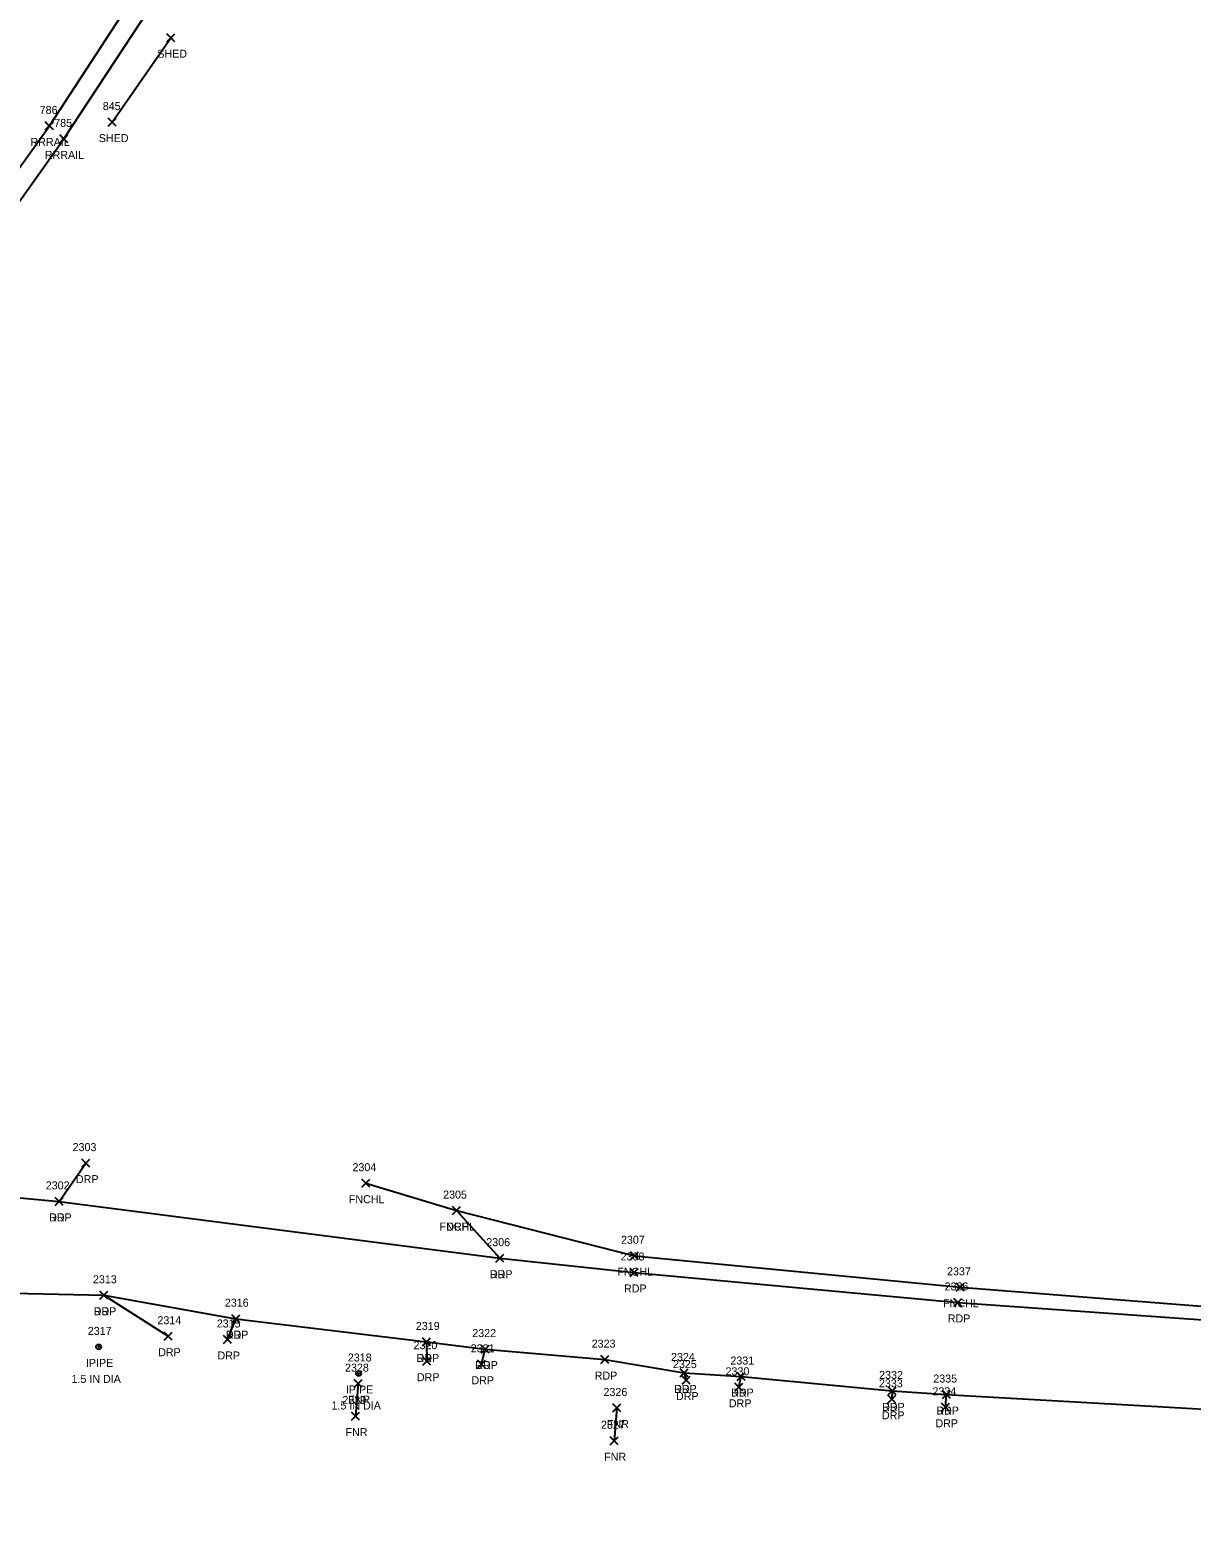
# Model space of a CAD drawing. Extents: x 1767353 to 1772625, y 740790 to 747702.
# Drawn here: x 1770625.6 to 1770915.9, y 742358.6 to 742730.2 of the extents above; entities that cross this region are included whole.
import ezdxf

# ---------------------------------------------------------------- set-up
doc = ezdxf.new("R2010")
doc.units = 0
for name, color, linetype in [('L_A', 7, 'Continuous'), ('L_I', 7, 'Continuous'), ('L_TIC', 7, 'Continuous'), ('LBC', 7, 'Continuous'), ('LFNC', 7, 'Continuous'), ('M_A', 7, 'Continuous'), ('M_C', 7, 'Continuous'), ('M_I', 7, 'Continuous'), ('MPIP', 7, 'Continuous'), ('P_A', 7, 'Continuous'), ('P_I', 7, 'Continuous'), ('P_TIC', 7, 'Continuous'), ('PET', 7, 'Continuous'), ('R_A', 7, 'Continuous'), ('R_I', 7, 'Continuous'), ('R_TIC', 7, 'Continuous'), ('RDP', 7, 'Continuous'), ('RR', 7, 'Continuous')]:
    doc.layers.add(name, color=color, linetype=linetype)

msp = doc.modelspace()

# ---------------------------------------------------------------- linework, layer by layer
at = {"layer": 'L_TIC'}
for points in [[(1770659.86, 742727.2), (1770661.86, 742729.2)], [(1770661.86, 742727.2), (1770659.86, 742729.2)], [(1770645.24, 742706.1), (1770647.24, 742708.1)], [(1770647.24, 742706.1), (1770645.24, 742708.1)], [(1770708.62, 742440.85), (1770710.62, 742442.85)], [(1770710.62, 742440.85), (1770708.62, 742442.85)], [(1770731.27, 742434), (1770733.27, 742436)], [(1770733.27, 742434), (1770731.27, 742436)], [(1770775.72, 742422.71), (1770777.72, 742424.71)], [(1770777.72, 742422.71), (1770775.72, 742424.71)], [(1770857.12, 742414.82), (1770859.12, 742416.82)], [(1770859.12, 742414.82), (1770857.12, 742416.82)], [(1770706.67, 742390.75), (1770708.67, 742392.75)], [(1770708.67, 742390.75), (1770706.67, 742392.75)], [(1770771.33, 742384.66), (1770773.33, 742386.66)], [(1770773.33, 742384.66), (1770771.33, 742386.66)], [(1770706.01, 742382.63), (1770708.01, 742384.63)], [(1770708.01, 742382.63), (1770706.01, 742384.63)], [(1770770.64, 742376.47), (1770772.64, 742378.47)], [(1770772.64, 742376.47), (1770770.64, 742378.47)]]:
    msp.add_lwpolyline(points, dxfattribs=at)
at = {"layer": 'LBC'}
msp.add_lwpolyline([(1770646.24, 742707.1), (1770660.86, 742728.2)], dxfattribs=at)
at = {"layer": 'LFNC'}
for points in [[(1770709.62, 742441.85), (1770732.27, 742435), (1770776.72, 742423.71), (1770858.12, 742415.82), (1770944.87, 742409.03), (1770965.3, 742411.95), (1770974.89, 742413.7), (1770984.8, 742417.23), (1770993.55, 742422.55), (1771009.31, 742433.08), (1771022.79, 742448.82), (1771027.82, 742457.07), (1771031.96, 742466.17), (1771043.36, 742521.94), (1771054.49, 742575.63), (1771058.48, 742593.36), (1771072.95, 742667.16), (1771097.46, 742789.3), (1771131.95, 742961.2), (1771147.21, 743037.58), (1771136.95, 743059.9)], [(1770707.67, 742391.75), (1770707.01, 742383.63)], [(1770772.33, 742385.66), (1770771.64, 742377.47)]]:
    msp.add_lwpolyline(points, dxfattribs=at)
at = {"layer": 'MPIP'}
for centre, radius in [((1770642.83, 742400.93), 0.625), ((1770642.83, 742400.93), 0.0833), ((1770707.8, 742394.28), 0.625), ((1770707.8, 742394.28), 0.0833)]:
    msp.add_circle(centre, radius, dxfattribs=at)
at = {"layer": 'P_TIC'}
for points in [[(1770631.97, 742436.3), (1770633.97, 742438.3)], [(1770633.97, 742436.3), (1770631.97, 742438.3)], [(1770742.12, 742422.11), (1770744.12, 742424.11)], [(1770744.12, 742422.11), (1770742.12, 742424.11)], [(1770775.64, 742418.53), (1770777.64, 742420.53)], [(1770777.64, 742418.53), (1770775.64, 742420.53)], [(1770643.11, 742412.83), (1770645.11, 742414.83)], [(1770645.11, 742412.83), (1770643.11, 742414.83)], [(1770856.56, 742411.05), (1770858.56, 742413.05)], [(1770858.56, 742411.05), (1770856.56, 742413.05)], [(1770676.13, 742406.98), (1770678.13, 742408.98)], [(1770678.13, 742406.98), (1770676.13, 742408.98)], [(1770723.81, 742401.17), (1770725.81, 742403.17)], [(1770725.81, 742401.17), (1770723.81, 742403.17)], [(1770738.48, 742399.39), (1770740.48, 742401.39)], [(1770740.48, 742399.39), (1770738.48, 742401.39)], [(1770768.32, 742396.75), (1770770.32, 742398.75)], [(1770770.32, 742396.75), (1770768.32, 742398.75)], [(1770788.15, 742393.42), (1770790.15, 742395.42)], [(1770790.15, 742393.42), (1770788.15, 742395.42)], [(1770802.42, 742392.52), (1770804.42, 742394.52)], [(1770804.42, 742392.52), (1770802.42, 742394.52)], [(1770840.15, 742388.93), (1770842.15, 742390.93)], [(1770842.15, 742388.93), (1770840.15, 742390.93)], [(1770853.69, 742388.02), (1770855.69, 742390.02)], [(1770855.69, 742388.02), (1770853.69, 742390.02)]]:
    msp.add_lwpolyline(points, dxfattribs=at)
at = {"layer": 'PET'}
for points in [[(1770560.4, 742444.06), (1770632.97, 742437.3), (1770743.12, 742423.11), (1770776.64, 742419.53), (1770857.56, 742412.05), (1770944.68, 742405.88), (1770965.1, 742405.17), (1770982.29, 742409.19), (1770994.69, 742414.12), (1771009.86, 742423.89), (1771022.38, 742435.96), (1771030.92, 742448.1), (1771037.68, 742466.88), (1771049.26, 742520.7), (1771064.29, 742592.13), (1771079.17, 742665.68), (1771104.37, 742787.53)], [(1770558.07, 742420.21), (1770594.59, 742416.67), (1770610.1, 742414.61), (1770644.11, 742413.83), (1770677.13, 742407.98), (1770724.81, 742402.17), (1770739.48, 742400.39), (1770769.32, 742397.75), (1770789.15, 742394.42), (1770803.42, 742393.52), (1770841.15, 742389.93), (1770854.69, 742389.02), (1770980.6, 742381.86), (1771012.22, 742378.21), (1771016.26, 742375.6), (1771018.35, 742372.34), (1771016.91, 742361.43)]]:
    msp.add_lwpolyline(points, dxfattribs=at)
at = {"layer": 'R_TIC'}
for points in [[(1770629.52, 742705.14), (1770631.52, 742707.14)], [(1770631.52, 742705.14), (1770629.52, 742707.14)], [(1770633.11, 742701.9), (1770635.11, 742703.9)], [(1770635.11, 742701.9), (1770633.11, 742703.9)], [(1770638.67, 742445.87), (1770640.67, 742447.87)], [(1770640.67, 742445.87), (1770638.67, 742447.87)], [(1770631.97, 742436.3), (1770633.97, 742438.3)], [(1770633.97, 742436.3), (1770631.97, 742438.3)], [(1770731.27, 742434), (1770733.27, 742436)], [(1770733.27, 742434), (1770731.27, 742436)], [(1770742.12, 742422.11), (1770744.12, 742424.11)], [(1770744.12, 742422.11), (1770742.12, 742424.11)], [(1770643.11, 742412.83), (1770645.11, 742414.83)], [(1770645.11, 742412.83), (1770643.11, 742414.83)], [(1770676.13, 742406.98), (1770678.13, 742408.98)], [(1770678.13, 742406.98), (1770676.13, 742408.98)], [(1770659.22, 742402.6), (1770661.22, 742404.6)], [(1770661.22, 742402.6), (1770659.22, 742404.6)], [(1770674.06, 742401.78), (1770676.06, 742403.78)], [(1770676.06, 742401.78), (1770674.06, 742403.78)], [(1770723.81, 742401.17), (1770725.81, 742403.17)], [(1770725.81, 742401.17), (1770723.81, 742403.17)], [(1770738.48, 742399.39), (1770740.48, 742401.39)], [(1770740.48, 742399.39), (1770738.48, 742401.39)], [(1770723.88, 742396.36), (1770725.88, 742398.36)], [(1770725.88, 742396.36), (1770723.88, 742398.36)], [(1770737.53, 742395.58), (1770739.53, 742397.58)], [(1770739.53, 742395.58), (1770737.53, 742397.58)], [(1770788.15, 742393.42), (1770790.15, 742395.42)], [(1770790.15, 742393.42), (1770788.15, 742395.42)], [(1770788.63, 742391.63), (1770790.63, 742393.63)], [(1770790.63, 742391.63), (1770788.63, 742393.63)], [(1770802.42, 742392.52), (1770804.42, 742394.52)], [(1770804.42, 742392.52), (1770802.42, 742394.52)], [(1770801.85, 742389.83), (1770803.85, 742391.83)], [(1770803.85, 742389.83), (1770801.85, 742391.83)], [(1770840.15, 742388.93), (1770842.15, 742390.93)], [(1770842.15, 742388.93), (1770840.15, 742390.93)], [(1770853.69, 742388.02), (1770855.69, 742390.02)], [(1770855.69, 742388.02), (1770853.69, 742390.02)], [(1770840.1, 742386.83), (1770842.1, 742388.83)], [(1770842.1, 742386.83), (1770840.1, 742388.83)], [(1770853.48, 742384.83), (1770855.48, 742386.83)], [(1770855.48, 742384.83), (1770853.48, 742386.83)]]:
    msp.add_lwpolyline(points, dxfattribs=at)
at = {"layer": 'RDP'}
for points in [[(1770632.97, 742437.3), (1770639.67, 742446.87)], [(1770732.27, 742435), (1770743.12, 742423.11)], [(1770644.11, 742413.83), (1770660.22, 742403.6)], [(1770675.06, 742402.78), (1770677.13, 742407.98)], [(1770724.81, 742402.17), (1770724.88, 742397.36)], [(1770738.53, 742396.58), (1770739.48, 742400.39)], [(1770789.15, 742394.42), (1770789.63, 742392.63)], [(1770802.85, 742390.83), (1770803.42, 742393.52)], [(1770841.15, 742389.93), (1770841.1, 742387.83)], [(1770854.48, 742385.83), (1770854.69, 742389.02)]]:
    msp.add_lwpolyline(points, dxfattribs=at)
at = {"layer": 'RR'}
for points in [[(1770271.52, 742143.69), (1770280.69, 742174.18), (1770289.74, 742198.6), (1770296.52, 742214.73), (1770308.93, 742241.95), (1770324.06, 742274.04), (1770340.68, 742308.04), (1770360.15, 742345.64), (1770381.03, 742382.61), (1770407.02, 742424.16), (1770425.18, 742450.58), (1770450.26, 742483.52), (1770473.18, 742510.79), (1770518.15, 742562.81), (1770572.7, 742627.85), (1770598.36, 742661.22), (1770630.52, 742706.14), (1770655.11, 742743.9), (1770674.5, 742775.55), (1770683.79, 742791.45), (1770706.15, 742833.16), (1770731.07, 742883.64), (1770775.22, 742979.87)], [(1770275.73, 742142.21), (1770285.7, 742173.47), (1770294.36, 742196.77), (1770301.28, 742213.26), (1770313.54, 742240.29), (1770328.52, 742271.98), (1770345.02, 742305.68), (1770363.97, 742342.43), (1770385.56, 742380.58), (1770410.92, 742420.89), (1770428.56, 742446.86), (1770454.89, 742481.33), (1770476.7, 742507.31), (1770522.14, 742559.86), (1770576.25, 742624.32), (1770602.26, 742658.04), (1770634.11, 742702.9), (1770659.93, 742742.21), (1770678.83, 742773.23), (1770687.73, 742788.35), (1770710.35, 742830.29), (1770735.06, 742880.72), (1770779.65, 742978.02)]]:
    msp.add_lwpolyline(points, dxfattribs=at)

# ---------------------------------------------------------------- texts
at = {"layer": 'L_A'}
for s, p in [('SHED', (1770657.5, 742723.2)), ('SHED', (1770642.88, 742702.1)), ('FNCHL', (1770705.37, 742436.85)), ('FNCHL', (1770728.01, 742430)), ('FNCHL', (1770772.47, 742418.71)), ('FNCHL', (1770853.87, 742410.82)), ('FNR', (1770705.2, 742386.75)), ('FNR', (1770769.87, 742380.66)), ('FNR', (1770704.55, 742378.63)), ('FNR', (1770769.18, 742372.47))]:
    msp.add_text(s, height=2, dxfattribs=at).set_placement(p)
at = {"layer": 'L_I'}
for s, p in [('845', (1770643.88, 742710.1)), ('2304', (1770706.28, 742444.85)), ('2305', (1770728.93, 742438)), ('2307', (1770773.38, 742426.71)), ('2337', (1770854.86, 742418.82)), ('2328', (1770704.41, 742394.75)), ('2326', (1770769.01, 742388.66)), ('2329', (1770703.75, 742386.63)), ('2327', (1770768.38, 742380.47))]:
    msp.add_text(s, height=2, dxfattribs=at).set_placement(p)
at = {"layer": 'M_A'}
for p in [(1770639.66, 742395.93), (1770704.64, 742389.28)]:
    msp.add_text('IPIPE', height=2, dxfattribs=at).set_placement(p)
at = {"layer": 'M_C'}
for p in [(1770636.06, 742391.93), (1770701.04, 742385.28)]:
    msp.add_text('1.5 IN DIA', height=2, dxfattribs=at).set_placement(p)
at = {"layer": 'M_I'}
for s, p in [('2317', (1770640.13, 742403.93)), ('2318', (1770705.11, 742397.28))]:
    msp.add_text(s, height=2, dxfattribs=at).set_placement(p)
at = {"layer": 'P_A'}
for p in [(1770630.46, 742432.3), (1770740.61, 742418.11), (1770774.13, 742414.53), (1770641.6, 742408.83), (1770855.05, 742407.05), (1770674.62, 742402.98), (1770722.3, 742397.17), (1770736.96, 742395.39), (1770766.81, 742392.75), (1770786.64, 742389.42), (1770800.9, 742388.52), (1770838.64, 742384.93), (1770852.18, 742384.02)]:
    msp.add_text('RDP', height=2, dxfattribs=at).set_placement(p)
at = {"layer": 'P_I'}
for s, p in [('2302', (1770629.63, 742440.3)), ('2306', (1770739.72, 742426.11)), ('2308', (1770773.3, 742422.53)), ('2313', (1770641.42, 742416.83)), ('2336', (1770854.25, 742415.05)), ('2316', (1770674.38, 742410.98)), ('2319', (1770722.11, 742405.17)), ('2322', (1770736.22, 742403.39)), ('2323', (1770766.06, 742400.75)), ('2324', (1770785.89, 742397.42)), ('2331', (1770800.72, 742396.52)), ('2332', (1770837.89, 742392.93)), ('2335', (1770851.43, 742392.02))]:
    msp.add_text(s, height=2, dxfattribs=at).set_placement(p)
at = {"layer": 'R_A'}
for s, p in [('RRRAIL', (1770625.81, 742701.14)), ('RRRAIL', (1770629.4, 742697.9)), ('DRP', (1770637.16, 742441.87)), ('DRP', (1770630.46, 742432.3)), ('DRP', (1770729.75, 742430)), ('DRP', (1770740.61, 742418.11)), ('DRP', (1770641.6, 742408.83)), ('DRP', (1770674.62, 742402.98)), ('DRP', (1770657.71, 742398.6)), ('DRP', (1770672.54, 742397.78)), ('DRP', (1770722.3, 742397.17)), ('DRP', (1770736.96, 742395.39)), ('DRP', (1770722.37, 742392.36)), ('DRP', (1770736.01, 742391.58)), ('DRP', (1770786.64, 742389.42)), ('DRP', (1770787.12, 742387.63)), ('DRP', (1770800.9, 742388.52)), ('DRP', (1770800.34, 742385.83)), ('DRP', (1770838.64, 742384.93)), ('DRP', (1770852.18, 742384.02)), ('DRP', (1770838.59, 742382.83)), ('DRP', (1770851.97, 742380.83))]:
    msp.add_text(s, height=2, dxfattribs=at).set_placement(p)
at = {"layer": 'R_I'}
for s, p in [('786', (1770628.11, 742709.14)), ('785', (1770631.74, 742705.9)), ('2303', (1770636.33, 742449.87)), ('2302', (1770629.63, 742440.3)), ('2305', (1770728.93, 742438)), ('2306', (1770739.72, 742426.11)), ('2313', (1770641.42, 742416.83)), ('2316', (1770674.38, 742410.98)), ('2314', (1770657.53, 742406.6)), ('2315', (1770672.36, 742405.78)), ('2319', (1770722.11, 742405.17)), ('2322', (1770736.22, 742403.39)), ('2320', (1770721.54, 742400.36)), ('2321', (1770735.83, 742399.58)), ('2324', (1770785.89, 742397.42)), ('2325', (1770786.37, 742395.63)), ('2331', (1770800.72, 742396.52)), ('2330', (1770799.51, 742393.83)), ('2332', (1770837.89, 742392.93)), ('2335', (1770851.43, 742392.02)), ('2333', (1770837.84, 742390.83)), ('2334', (1770851.22, 742388.83))]:
    msp.add_text(s, height=2, dxfattribs=at).set_placement(p)

doc.saveas('drawing.dxf')
